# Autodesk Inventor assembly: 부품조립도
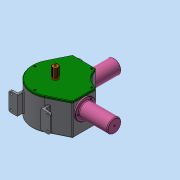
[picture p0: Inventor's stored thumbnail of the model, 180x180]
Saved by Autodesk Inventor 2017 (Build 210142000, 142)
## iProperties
Part Number: 부품조립도
Material: 일반
Document SubType Name: Assembly
Designer: MRC
Author: MRC
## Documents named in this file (13)
- C:\Users\MRC\Desktop\611109V1004\부품조립도.iam
- C:\Users\MRC\Desktop\611109V1004\본체.ipt
- C:\Users\MRC\Desktop\611109V1004\너트 M3.ipt
- C:\Users\MRC\Desktop\611109V1004\베어링 20 x 37 x 9.ipt
- C:\Users\MRC\Desktop\611109V1004\볼트 M3 x 12.ipt
- C:\Users\MRC\Desktop\611109V1004\실린더.ipt
- C:\Users\MRC\Desktop\611109V1004\앞커버.ipt
- C:\Users\MRC\Desktop\611109V1004\축.ipt
- C:\Users\MRC\Desktop\611109V1004\측정게이지.ipt
- C:\Users\MRC\Desktop\611109V1004\커넥팅로드 캡.ipt
- C:\Users\MRC\Desktop\611109V1004\커넥팅로드.ipt
- C:\Users\MRC\Desktop\611109V1004\피스톤 핀.ipt
- C:\Users\MRC\Desktop\611109V1004\피스톤.ipt
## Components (4 placed, 2 different names)
1. 피스톤 핀:1
2. 피스톤:1
3. 피스톤:2
4. 피스톤 핀:2
